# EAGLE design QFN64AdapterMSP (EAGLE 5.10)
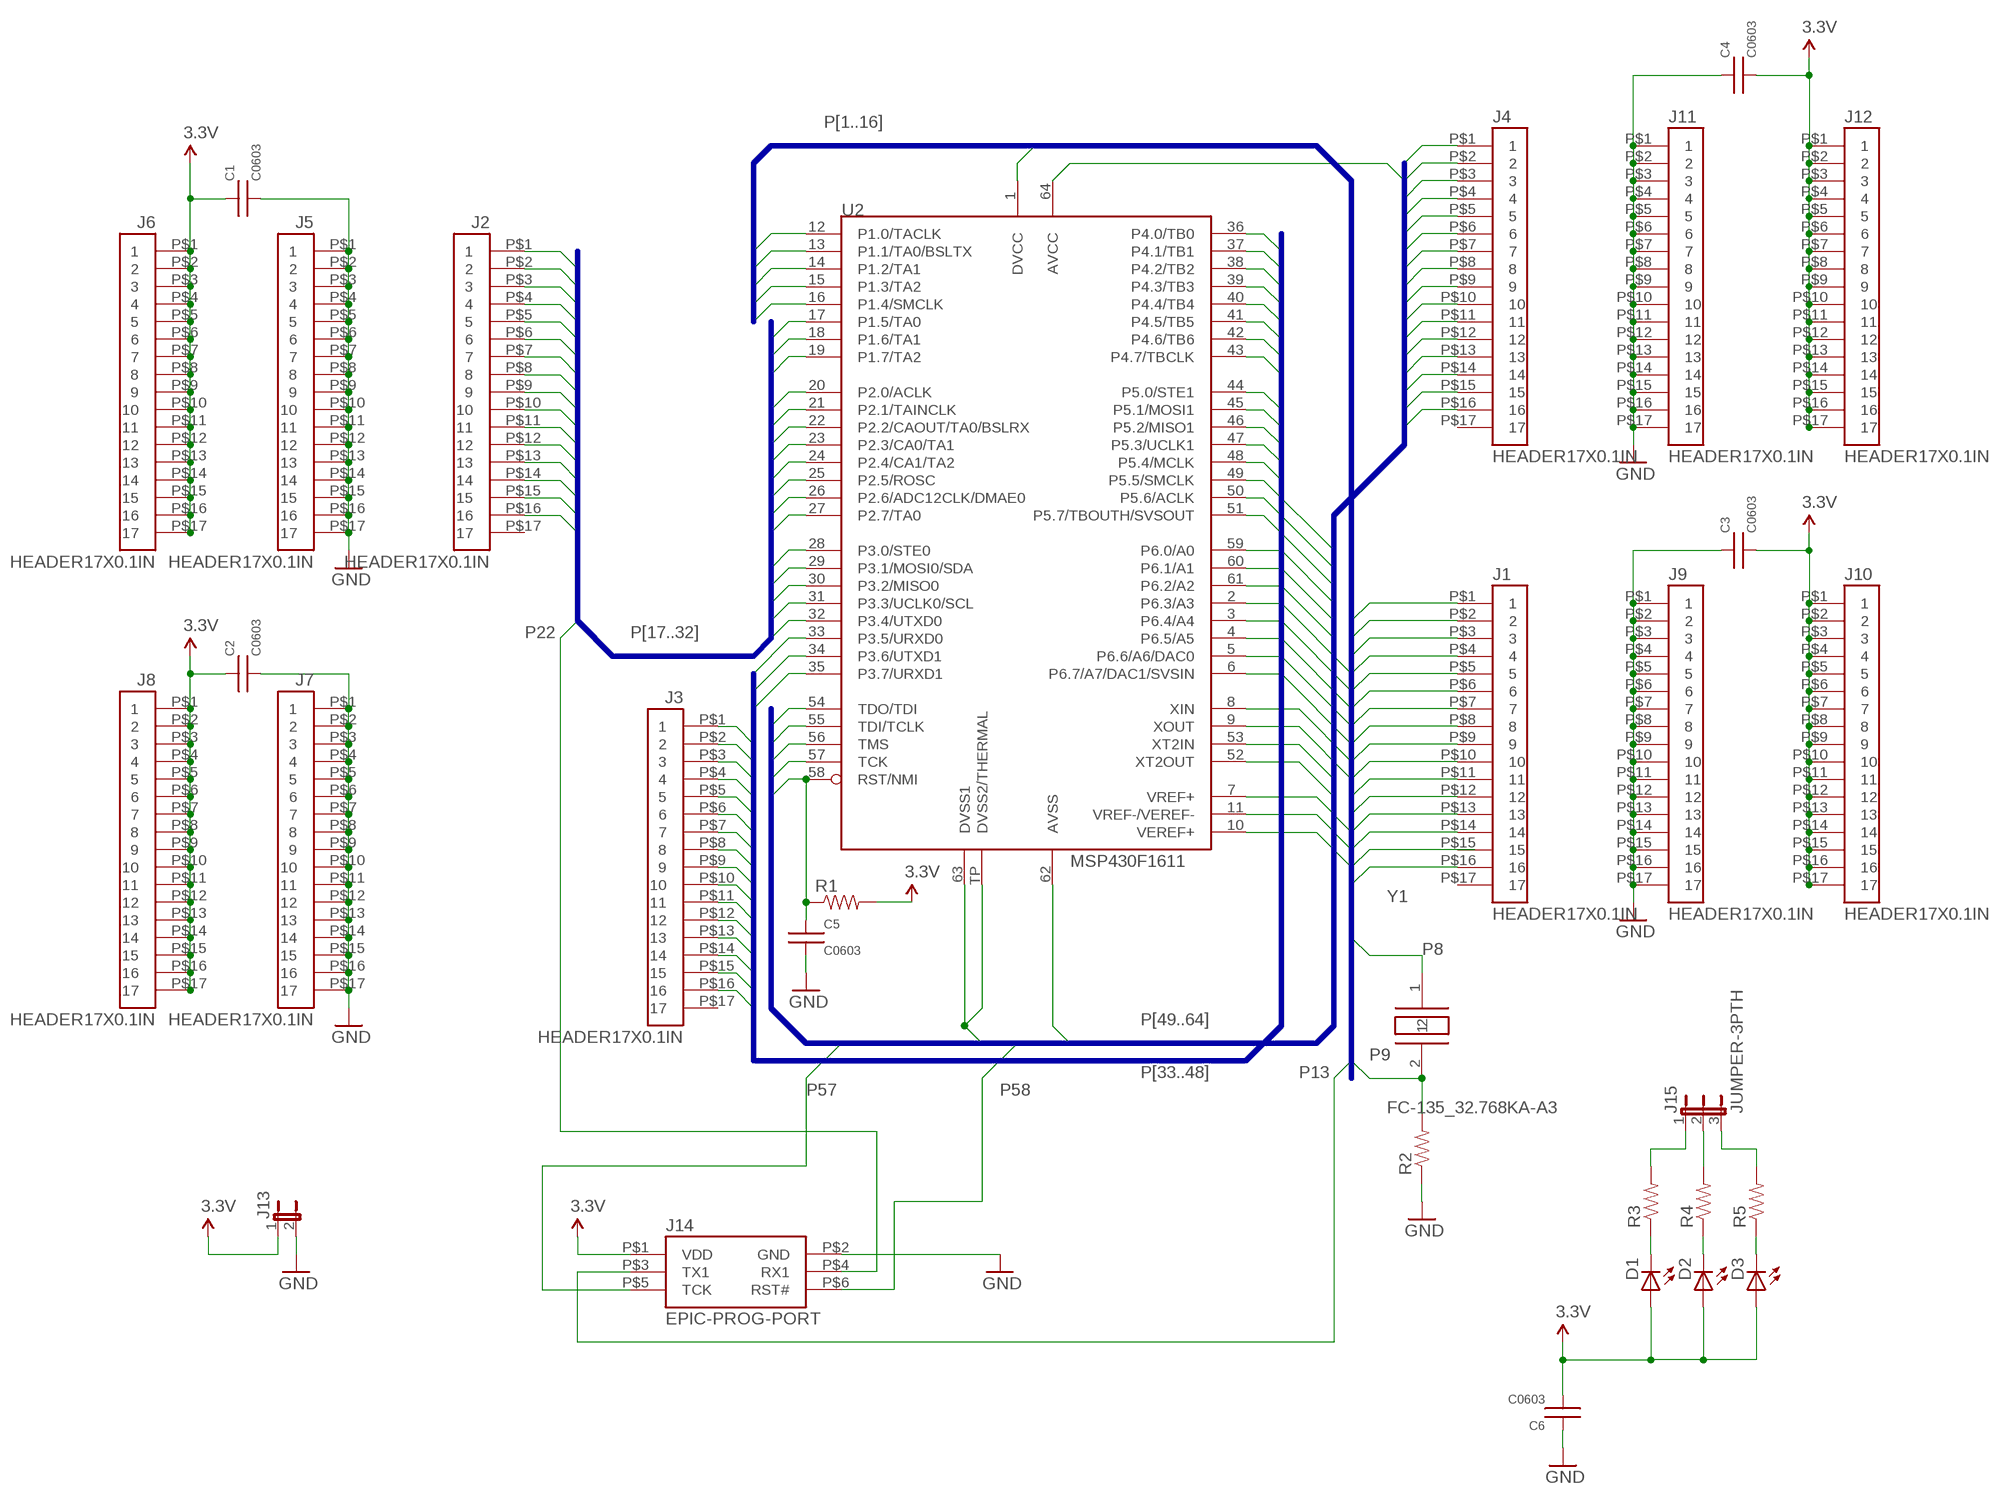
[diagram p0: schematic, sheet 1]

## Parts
C1  C0603  [C0603]
C2  C0603  [C0603]
C3  C0603  [C0603]
C4  C0603  [C0603]
C5  C0603  [C0603]
C6  C0603  [C0603]
D1  LED0603  [LED-0603]
D2  LED0603  [LED-0603]
D3  LED0603  [LED-0603]
J1  HEADER17X0.1IN  [HEADER17X0.1IN]
J2  HEADER17X0.1IN  [HEADER17X0.1IN]
J3  HEADER17X0.1IN  [HEADER17X0.1IN]
J4  HEADER17X0.1IN  [HEADER17X0.1IN]
J5  HEADER17X0.1IN  [HEADER17X0.1IN]
J6  HEADER17X0.1IN  [HEADER17X0.1IN]
J7  HEADER17X0.1IN  [HEADER17X0.1IN]
J8  HEADER17X0.1IN  [HEADER17X0.1IN]
J9  HEADER17X0.1IN  [HEADER17X0.1IN]
J10  HEADER17X0.1IN  [HEADER17X0.1IN]
J11  HEADER17X0.1IN  [HEADER17X0.1IN]
J12  HEADER17X0.1IN  [HEADER17X0.1IN]
J13  JUMPER-2PTH  [1X02]
J14  EPIC-PROG-PORT  [HEADER2X3X2MM]
J15  JUMPER-3PTH  [1X03]
R1  RESISTOR0603-RES  [0603-RES]
R2  RESISTOR0603-RES  [0603-RES]
R3  RESISTOR0603-RES  [0603-RES]
R4  RESISTOR0603-RES  [0603-RES]
R5  RESISTOR0603-RES  [0603-RES]
U2  MSP430F1611  [RTD(S-PQFP-N64)[VQFN64]]
Y1  FC-135_32.768KA-A3  [FC-135]

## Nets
3.3V: C1.1 C2.1 C3.2 C4.2 C6.2 D1.A D2.A D3.A J6.P$1 J6.P$2 J6.P$3 J6.P$4 J6.P$5 J6.P$6 J6.P$7 J6.P$8 J6.P$9 J6.P$10 J6.P$11 J6.P$12 J6.P$13 J6.P$14 J6.P$15 J6.P$16 J6.P$17 J8.P$1 J8.P$2 J8.P$3 J8.P$4 J8.P$5 J8.P$6 J8.P$7 J8.P$8 J8.P$9 J8.P$10 J8.P$11 J8.P$12 J8.P$13 J8.P$14 J8.P$15 J8.P$16 J8.P$17 J10.P$1 J10.P$2 J10.P$3 J10.P$4 J10.P$5 J10.P$6 J10.P$7 J10.P$8 J10.P$9 J10.P$10 J10.P$11 J10.P$12 J10.P$13 J10.P$14 J10.P$15 J10.P$16 J10.P$17 J12.P$1 J12.P$2 J12.P$3 J12.P$4 J12.P$5 J12.P$6 J12.P$7 J12.P$8 J12.P$9 J12.P$10 J12.P$11 J12.P$12 J12.P$13 J12.P$14 J12.P$15 J12.P$16 J12.P$17 J13.1 J14.P$1(VDD) R1.2
GND: C1.2 C2.2 C3.1 C4.1 C5.2 C6.1 J5.P$1 J5.P$2 J5.P$3 J5.P$4 J5.P$5 J5.P$6 J5.P$7 J5.P$8 J5.P$9 J5.P$10 J5.P$11 J5.P$12 J5.P$13 J5.P$14 J5.P$15 J5.P$16 J5.P$17 J7.P$1 J7.P$2 J7.P$3 J7.P$4 J7.P$5 J7.P$6 J7.P$7 J7.P$8 J7.P$9 J7.P$10 J7.P$11 J7.P$12 J7.P$13 J7.P$14 J7.P$15 J7.P$16 J7.P$17 J9.P$1 J9.P$2 J9.P$3 J9.P$4 J9.P$5 J9.P$6 J9.P$7 J9.P$8 J9.P$9 J9.P$10 J9.P$11 J9.P$12 J9.P$13 J9.P$14 J9.P$15 J9.P$16 J9.P$17 J11.P$1 J11.P$2 J11.P$3 J11.P$4 J11.P$5 J11.P$6 J11.P$7 J11.P$8 J11.P$9 J11.P$10 J11.P$11 J11.P$12 J11.P$13 J11.P$14 J11.P$15 J11.P$16 J11.P$17 J13.2 J14.P$2(GND) R2.1
N$1: D1.C R3.1
N$2: D2.C R4.1
N$3: D3.C R5.1
N$4: J15.1 R3.2
N$5: J15.2 R4.2
N$6: J15.3 R5.2
P1: J1.P$1 U2.1(DVCC)
P2: J1.P$2 U2.2(P6.3/A3)
P3: J1.P$3 U2.3(P6.4/A4)
P4: J1.P$4 U2.4(P6.5/A5)
P5: J1.P$5 U2.5(P6.6/A6/DAC0)
P6: J1.P$6 U2.6(P6.7/A7/DAC1/SVSIN)
P7: J1.P$7 U2.7(VREF+)
P8: J1.P$8 U2.8(XIN) Y1.1
P9: J1.P$9 R2.2 U2.9(XOUT) Y1.2
P10: J1.P$10 U2.10(VEREF+)
P11: J1.P$11 U2.11(VREF-/VEREF-)
P12: J1.P$12 U2.12(P1.0/TACLK)
P13: J1.P$13 J14.P$3(TX1) U2.13(P1.1/TA0/BSLTX)
P14: J1.P$14 U2.14(P1.2/TA1)
P15: J1.P$15 U2.15(P1.3/TA2)
P16: J1.P$16 U2.16(P1.4/SMCLK)
P17: J2.P$1 U2.17(P1.5/TA0)
P18: J2.P$2 U2.18(P1.6/TA1)
P19: J2.P$3 U2.19(P1.7/TA2)
P20: J2.P$4 U2.20(P2.0/ACLK)
P21: J2.P$5 U2.21(P2.1/TAINCLK)
P22: J2.P$6 J14.P$4(RX1) U2.22(P2.2/CAOUT/TA0/BSLRX)
P23: J2.P$7 U2.23(P2.3/CA0/TA1)
P24: J2.P$8 U2.24(P2.4/CA1/TA2)
P25: J2.P$9 U2.25(P2.5/ROSC)
P26: J2.P$10 U2.26(P2.6/ADC12CLK/DMAE0)
P27: J2.P$11 U2.27(P2.7/TA0)
P28: J2.P$12 U2.28(P3.0/STE0)
P29: J2.P$13 U2.29(P3.1/MOSI0/SDA)
P30: J2.P$14 U2.30(P3.2/MISO0)
P31: J2.P$15 U2.31(P3.3/UCLK0/SCL)
P32: J2.P$16 U2.32(P3.4/UTXD0)
P33: J3.P$1 U2.33(P3.5/URXD0)
P34: J3.P$2 U2.34(P3.6/UTXD1)
P35: J3.P$3 U2.35(P3.7/URXD1)
P36: J3.P$4 U2.36(P4.0/TB0)
P37: J3.P$5 U2.37(P4.1/TB1)
P38: J3.P$6 U2.38(P4.2/TB2)
P39: J3.P$7 U2.39(P4.3/TB3)
P40: J3.P$8 U2.40(P4.4/TB4)
P41: J3.P$9 U2.41(P4.5/TB5)
P42: J3.P$10 U2.42(P4.6/TB6)
P43: J3.P$11 U2.43(P4.7/TBCLK)
P44: J3.P$12 U2.44(P5.0/STE1)
P45: J3.P$13 U2.45(P5.1/MOSI1)
P46: J3.P$14 U2.46(P5.2/MISO1)
P47: J3.P$15 U2.47(P5.3/UCLK1)
P48: J3.P$16 U2.48(P5.4/MCLK)
P49: J4.P$1 U2.49(P5.5/SMCLK)
P50: J4.P$2 U2.50(P5.6/ACLK)
P51: J4.P$3 U2.51(P5.7/TBOUTH/SVSOUT)
P52: J4.P$4 U2.52(XT2OUT)
P53: J4.P$5 U2.53(XT2IN)
P54: J4.P$6 U2.54(TDO/TDI)
P55: J4.P$7 U2.55(TDI/TCLK)
P56: J4.P$8 U2.56(TMS)
P57: J4.P$9 J14.P$5(TCK) U2.57(TCK)
P58: C5.1 J4.P$10 J14.P$6(RST#) R1.1 U2.58(RST/NMI)
P59: J4.P$11 U2.59(P6.0/A0)
P60: J4.P$12 U2.60(P6.1/A1)
P61: J4.P$13 U2.61(P6.2/A2)
P62: J4.P$14 U2.62(AVSS)
P63: J4.P$15 U2.63(DVSS1) U2.TP(DVSS2/THERMAL)
P64: J4.P$16 U2.64(AVCC)
Unconnected: J1.P$17 J2.P$17 J3.P$17 J4.P$17

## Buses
P[17..32]
P[33..48]
P[49..64]
P[1..16]

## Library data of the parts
C1-C6 = umich:C
D1-D3 = umich:LED: LEDs
J1-J12 = berkeley-epic:HEADER17X0.1IN
J13 = umich:JUMPER-2: Jumper
J14 = berkeley-epic:EPIC-PROG-PORT
J15 = umich:JUMPER-3
R1-R5 = SparkFun:RESISTOR: Resistor
U2 = Thomas:MSP430F1611
Y1 = berkeley-epic:FC-135_32.768KA-A3

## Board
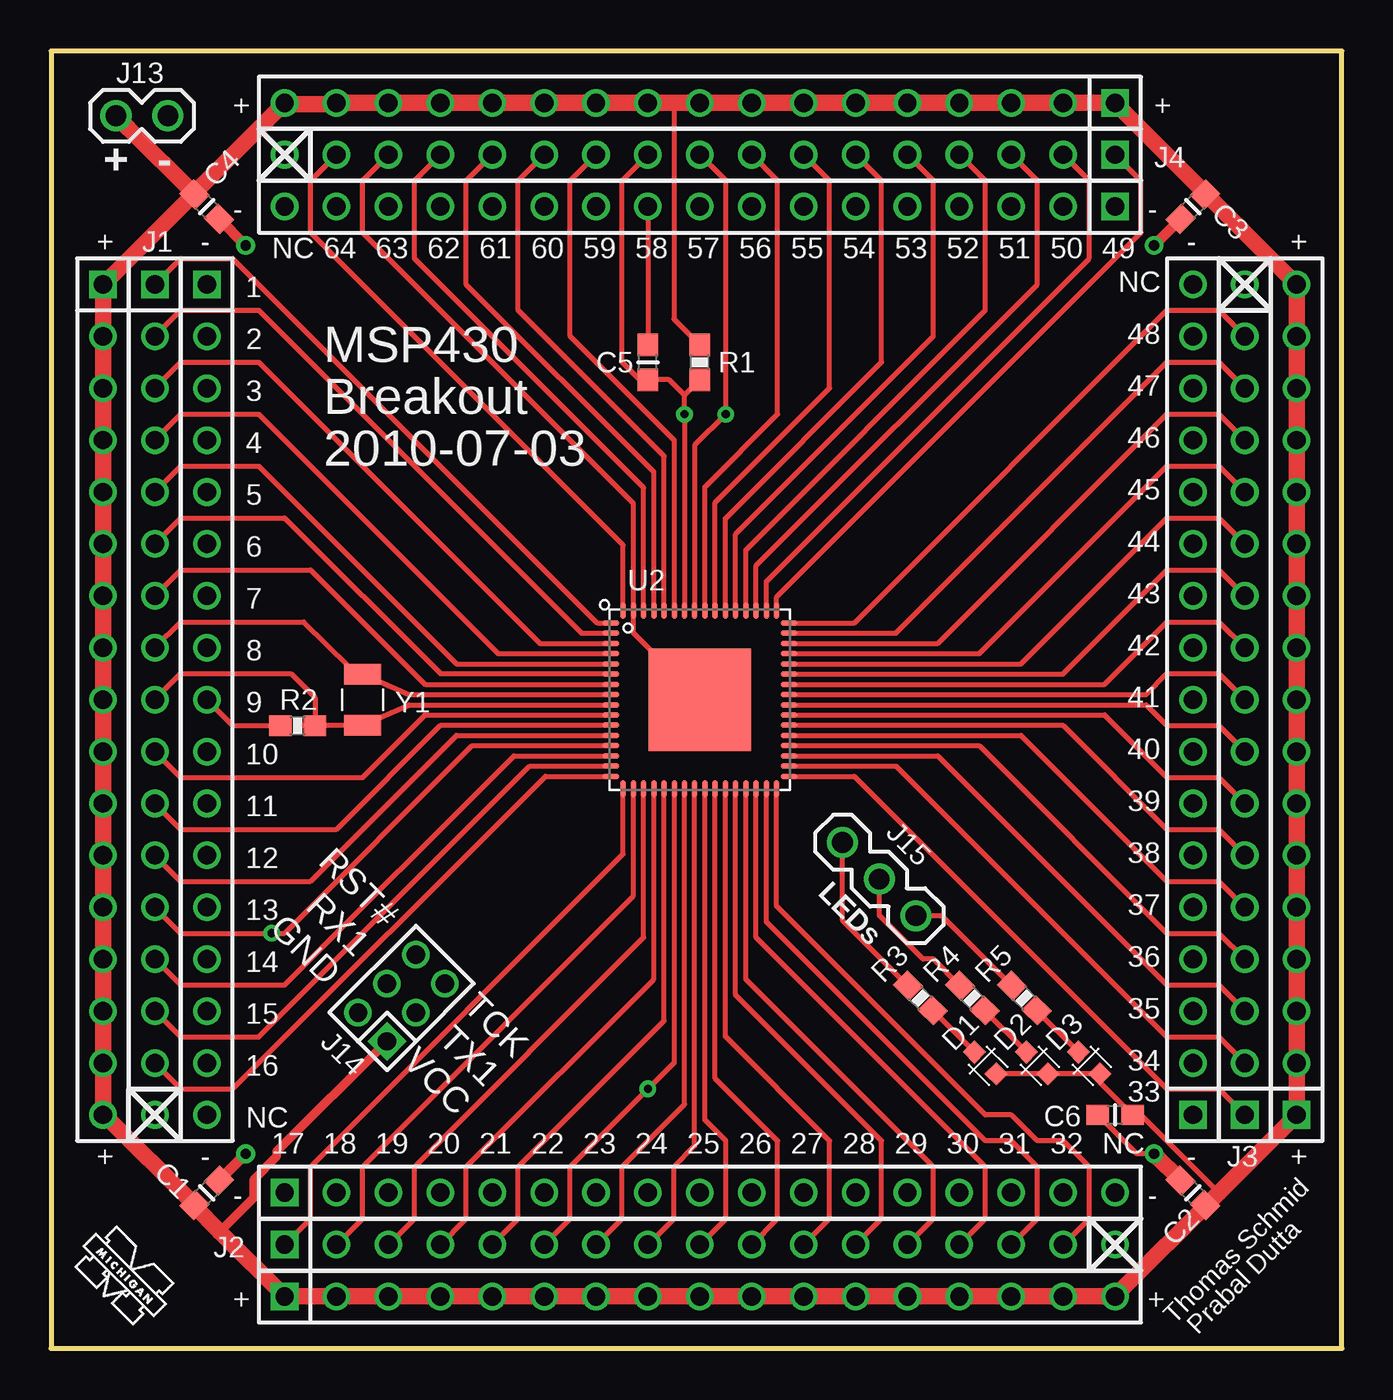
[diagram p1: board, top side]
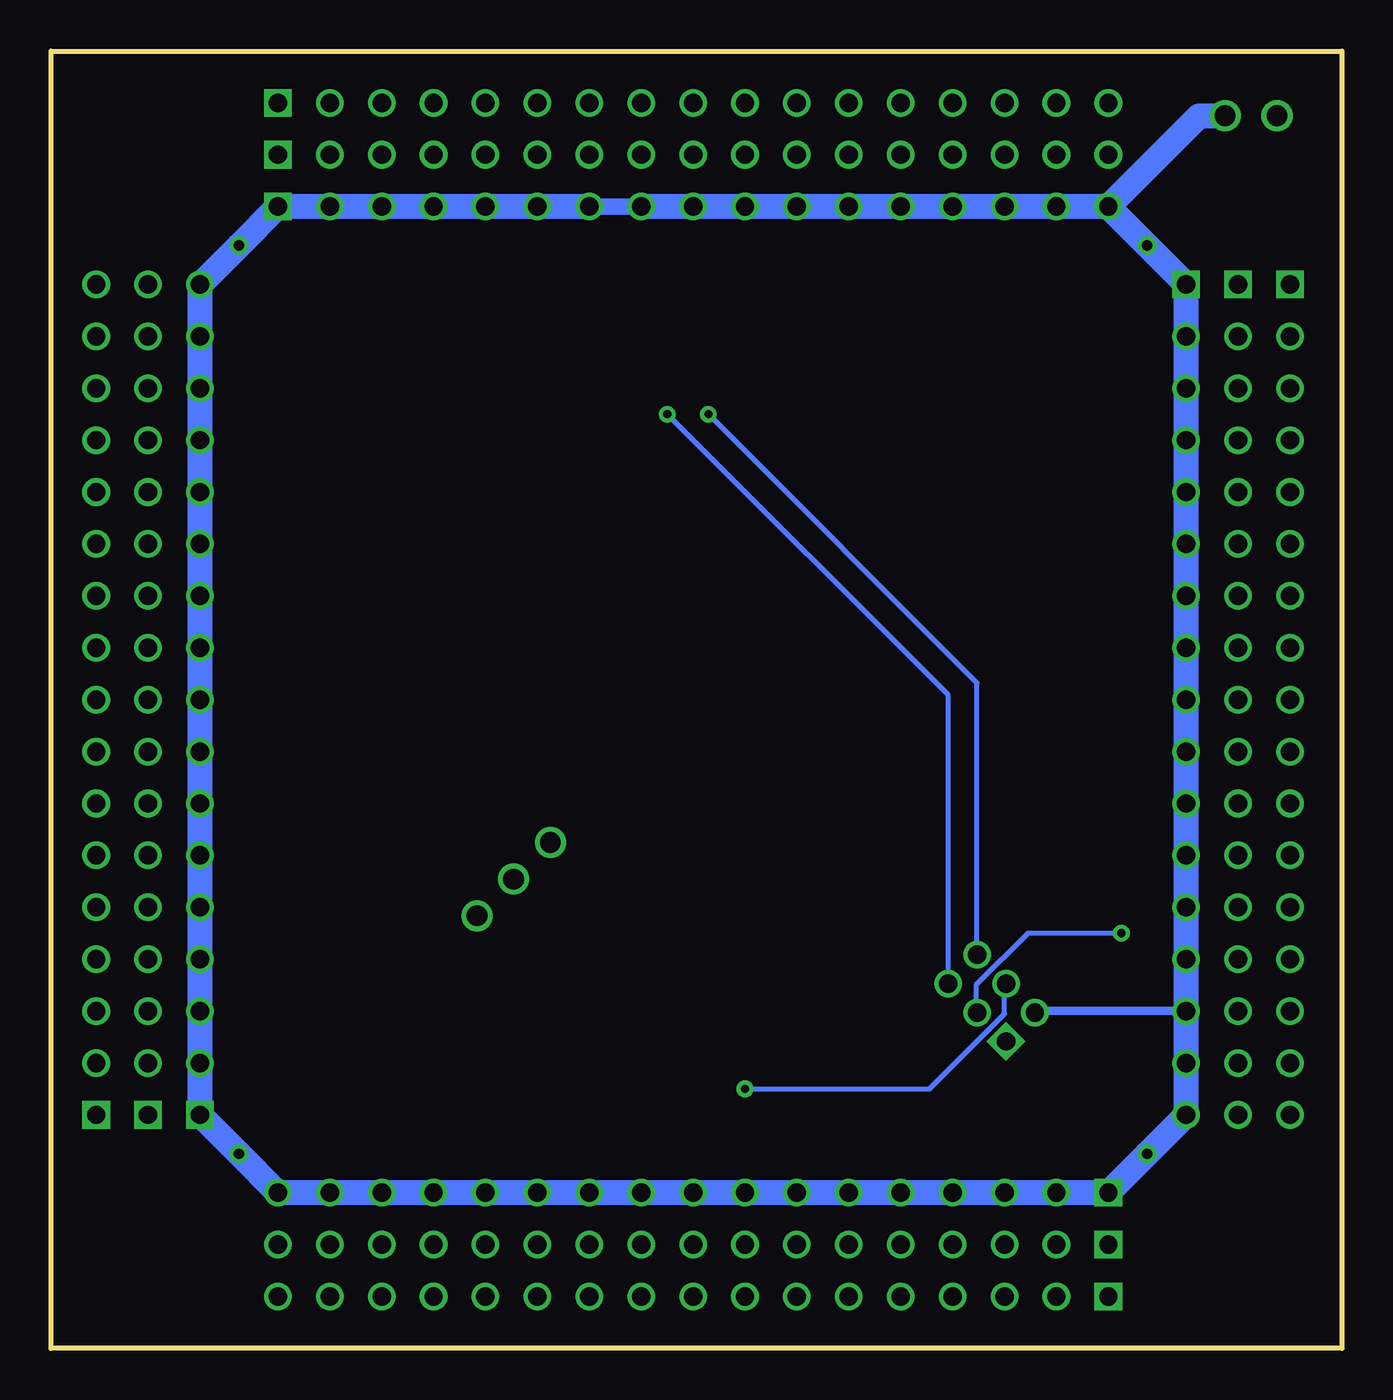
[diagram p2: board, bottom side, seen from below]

Size 63.17 x 63.49 mm. Coordinates in mm from the lower left corner, seen from the top.
Outline: 0,0 63.17,0 63.17,63.49 0,63.49 0,0
Copper layers (1*16): Top 0.0178mm / dielectric 1.4986mm / Bottom 0.0178mm
Design rules "SSC-EAGLE-2Lyr_v1.0.0.3": minimum track width 6mil, minimum drill 14mil, track to track 6mil, track to pad 6mil, pad to pad 6mil, via to via 6mil, smd to smd 6mil, copper to edge 20mil, drill to drill 16mil, minimum pad ring 8mil, minimum via ring 8mil, stop-mask expansion 3mil, vias tented up to drill 0mil, thermal gap 10mil

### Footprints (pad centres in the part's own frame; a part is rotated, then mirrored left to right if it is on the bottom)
C0603 = smd 1.1 x 1: 1 -0.85,0; 2 0.85,0
LED-0603 = smd 0.8 x 0.8: A 0,-0.75; C 0,0.75
HEADER17X0.1IN = drill 0.9 square: P$1 -20.32,0 | drill 0.9 round: P$2 -17.78,0; P$3 -15.24,0; P$4 -12.7,0; P$5 -10.16,0; P$6 -7.62,0; P$7 -5.08,0; P$8 -2.54,0; P$9 0,0; P$10 2.54,0; P$11 5.08,0; P$12 7.62,0; P$13 10.16,0; P$14 12.7,0; P$15 15.24,0; P$16 17.78,0; P$17 20.32,0
1X02 = drill 1.016 round: 1 0,0; 2 2.54,0
HEADER2X3X2MM = drill 0.9 square: P$1 -1,2 | drill 0.9 round: P$2 1,2; P$3 -1,0; P$4 1,0; P$5 -1,-2; P$6 1,-2
1X03 = drill 1.016 round: 1 0,0; 2 2.54,0; 3 5.08,0
0603-RES = smd 1.1 x 1: 1 -0.85,0; 2 0.85,0
RTD(S-PQFP-N64)[VQFN64] = smd 0.825 x 0.28: 1 -4.36,3.75; 2 -4.36,3.25; 3 -4.36,2.75; 4 -4.36,2.25; 5 -4.36,1.75; 6 -4.36,1.25; 7 -4.36,0.75; 8 -4.36,0.25; 9 -4.36,-0.25; 10 -4.36,-0.75; 11 -4.36,-1.25; 12 -4.36,-1.75; 13 -4.36,-2.25; 14 -4.36,-2.75; 15 -4.36,-3.25; 16 -4.36,-3.75; 33 4.36,-3.75; 34 4.36,-3.25; 35 4.36,-2.75; 36 4.36,-2.25; 37 4.36,-1.75; 38 4.36,-1.25; 39 4.36,-0.75; 40 4.36,-0.25; 41 4.36,0.25; 42 4.36,0.75; 43 4.36,1.25; 44 4.36,1.75; 45 4.36,2.25; 46 4.36,2.75; 47 4.36,3.25; 48 4.36,3.75 | smd 0.28 x 0.825: 17 -3.75,-4.36; 18 -3.25,-4.36; 19 -2.75,-4.36; 20 -2.25,-4.36; 21 -1.75,-4.36; 22 -1.25,-4.36; 23 -0.75,-4.36; 24 -0.25,-4.36; 25 0.25,-4.36; 26 0.75,-4.36; 27 1.25,-4.36; 28 1.75,-4.36; 29 2.25,-4.36; 30 2.75,-4.36; 31 3.25,-4.36; 32 3.75,-4.36; 49 3.75,4.36; 50 3.25,4.36; 51 2.75,4.36; 52 2.25,4.36; 53 1.75,4.36; 54 1.25,4.36; 55 0.75,4.36; 56 0.25,4.36; 57 -0.25,4.36; 58 -0.75,4.36; 59 -1.25,4.36; 60 -1.75,4.36; 61 -2.25,4.36; 62 -2.75,4.36; 63 -3.25,4.36; 64 -3.75,4.36 | smd 5 x 5: TP 0,0
FC-135 = smd 1 x 1.8: 1 -1.25,0; 2 1.25,0

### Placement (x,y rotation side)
C1  7.62,7.62 45 top
C2  55.88,7.62 135 top
C3  55.88,55.88 45 top
C4  7.62,55.88 135 top
C5  29.21,48.26 90 top
C6  52.07,11.43 0 top
D1  45.72,13.97 45 top
D2  48.26,13.97 45 top
D3  50.8,13.97 45 top
J1  5.08,31.75 270 top
J2  31.75,5.08 0 top
J3  58.42,31.75 90 top
J4  31.75,58.42 180 top
J5  31.75,7.62 0 top
J6  31.75,2.54 0 top
J7  55.88,31.75 90 top
J8  60.96,31.75 90 top
J9  7.62,31.75 270 top
J10  2.54,31.75 270 top
J11  31.75,55.88 180 top
J12  31.75,60.96 180 top
J13  3.17,60.33 0 top
J14  17.14,17.14 135 top
J15  38.73,24.77 315 top
R1  31.75,48.26 90 top
R2  12.06,30.48 0 top
R3  42.55,17.14 135 top
R4  45.09,17.14 135 top
R5  47.62,17.14 135 top
U2  31.75,31.75 0 top
U$2  [UMICH]  0.64,4.19 315 top
Y1  15.24,31.75 270 top

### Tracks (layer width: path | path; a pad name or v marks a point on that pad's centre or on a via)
3.3V
  Top 0.254: R1.2 30.48,50.38 30.48,60.96 | C2.1 57.08,7.62 57.15,7.62 53.34,11.43 C6.2 51.33,13.02 D3.A D2.A D1.A | J8.P$17 60.89,52.07 C3.2 | J12.P$16 13.9,60.89 | J12.P$10 J12.P$9
  Top 0.406: 8.26,5.71 9.91,7.37 9.91,8.26 11.05,9.4 11.05,9.63 J14.P$1
  Top 0.508: 2.61,11.43 J10.P$17 | C1.1 7.02,6.95 | J10.P$13 J10.P$12 2.54,25.4 | C4.2 11.43,60.89 J12.P$17 J12.P$16 | J12.P$10 30.48,60.96 J12.P$9 J12.P$8 | J12.P$5 J12.P$4 J12.P$3
  Top 0.813: 7.02,6.95 8.26,5.71 J6.P$1 J6.P$2 J6.P$3 J6.P$4 J6.P$5 J6.P$6 J6.P$7 J6.P$8 J6.P$9 J6.P$10 J6.P$11 J6.P$12 J6.P$13 J6.P$14 J6.P$15 J6.P$16 J6.P$17 57.15,7.62 J8.P$1 J8.P$2 J8.P$3 J8.P$4 J8.P$5 J8.P$6 J8.P$7 J8.P$8 J8.P$9 J8.P$10 J8.P$11 J8.P$12 J8.P$13 J8.P$14 J8.P$15 J8.P$16 J8.P$17 J12.P$1 J12.P$2 J12.P$3 J12.P$5 J12.P$6 J12.P$7 J12.P$8 J12.P$10 J12.P$11 J12.P$12 J12.P$13 J12.P$14 J12.P$15 J12.P$16 | J10.P$17 J10.P$16 J10.P$15 J10.P$14 J10.P$13 2.54,25.4 J10.P$11 J10.P$10 J10.P$9 J10.P$8 J10.P$7 J10.P$6 J10.P$5 J10.P$4 J10.P$3 J10.P$2 J10.P$1 J12.P$17 | J13.1 3.81,59.69 C4.2 | C1.1 2.61,11.43 | 11.43,60.89 13.9,60.89
GND  (via drill 0.51)
  Top 0.254: R2.1 8.89,30.48 J9.P$9 | J11.P$10 C5.2 | v53.98,9.53 53.12,9.53 C6.1
  Top 0.508: C1.2 v9.53,9.53 | v9.53,53.98 C4.1 | v53.98,53.98 C3.1
  Top 0.813: v53.98,9.53 C2.2
  Bottom 0.406: J9.P$15 14.95,16.51 J14.P$2
  Bottom 0.508: J5.P$13 J5.P$14 J5.P$15
  Bottom 0.813: J11.P$8 J11.P$7
  Bottom 1.219: J11.P$17 J11.P$16 J11.P$15 J11.P$14 J11.P$13 J11.P$12 J11.P$11 J11.P$10 J11.P$9 J11.P$8 | J11.P$7 J11.P$6 J11.P$5 J11.P$4 J11.P$3 J11.P$2 J11.P$1 v53.98,53.98 J7.P$17 J7.P$16 J7.P$15 J7.P$14 J7.P$13 J7.P$12 J7.P$11 J7.P$10 J7.P$9 J7.P$8 J7.P$7 J7.P$6 J7.P$5 J7.P$4 J7.P$3 J7.P$2 J7.P$1 v53.98,9.53 J5.P$17 J5.P$16 J5.P$15 J5.P$13 J5.P$12 J5.P$11 J5.P$10 J5.P$9 J5.P$8 J5.P$7 J5.P$6 J5.P$5 J5.P$4 J5.P$3 J5.P$2 J5.P$1 v9.53,9.53 J9.P$17 J9.P$16 J9.P$15 J9.P$14 J9.P$13 J9.P$12 J9.P$11 J9.P$10 J9.P$9 J9.P$8 J9.P$7 J9.P$6 J9.P$5 J9.P$4 J9.P$3 J9.P$2 J9.P$1 v9.53,53.98 J11.P$17 | J11.P$17 6.99,60.33 J13.2
N$1
  Top 0.254: D1.C R3.1
N$2
  Top 0.254: D2.C R4.1
N$3
  Top 0.254: D3.C R5.1
N$4
  Top 0.254: J15.1 38.73,20.95 R3.2
N$5
  Top 0.254: J15.2 40.53,21.19 42.67,19.05 43.18,19.05 R4.2
N$6
  Top 0.254: J15.3 43.6,21.17 R5.2
P1
  Top 0.254: U2.1 26.73,35.5 8.89,53.34 6.35,53.34 J1.P$1
P2
  Top 0.254: U2.2 25.96,35 10.16,50.8 6.35,50.8 J1.P$2
P3
  Top 0.254: U2.3 23.92,34.5 10.16,48.26 6.35,48.26 J1.P$3
P4
  Top 0.254: U2.4 21.88,34 10.16,45.72 6.35,45.72 J1.P$4
P5
  Top 0.254: U2.5 19.84,33.5 10.16,43.18 6.35,43.18 J1.P$5
P6
  Top 0.254: J1.P$6 6.35,40.64 11.43,40.64 19.05,33.02 27.37,33.02 U2.6
P7
  Top 0.254: J1.P$7 6.35,38.1 12.7,38.1 18.3,32.5 U2.7
P8
  Top 0.254: U2.8 17.51,32 Y1.1 14.94,33 14.61,33.34 12.36,35.56 6.35,35.56 J1.P$8
P9
  Top 0.254: U2.9 17.51,31.5 Y1.2 12.3,30.5 R2.2 12.91,31.85 11.75,33.02 6.35,33.02 J1.P$9
P10
  Top 0.254: U2.10 18.3,31 15.24,27.94 6.35,27.94 J1.P$10
P11
  Top 0.254: U2.11 19.07,30.5 13.97,25.4 6.35,25.4 J1.P$11
P12
  Top 0.254: U2.12 19.84,30 12.7,22.86 6.35,22.86 J1.P$12
P13  (via drill 0.41)
  Top 0.254: U2.13 20.61,29.5 11.43,20.32 v10.79,20.32 6.35,20.32 J1.P$13
  Bottom 0.254: J14.P$3 17.85,16.45 17.91,16.51 17.91,17.78 15.37,20.32 v10.79,20.32
P14
  Top 0.254: U2.14 22.65,29 11.43,17.78 6.35,17.78 J1.P$14
P15
  Top 0.254: U2.15 23.42,28.5 10.16,15.24 6.35,15.24 J1.P$15
P16
  Top 0.254: U2.16 24.19,28 8.89,12.7 6.35,12.7 J1.P$16
P17
  Top 0.254: U2.17 28,24.19 12.7,8.89 12.7,6.35 J2.P$1
P18
  Top 0.254: U2.18 28.5,22.15 15.24,8.89 15.24,6.35 J2.P$2
P19
  Top 0.254: U2.19 29,20.11 17.78,8.89 17.78,6.35 J2.P$3
P20
  Top 0.254: U2.20 29.5,18.07 20.32,8.89 20.32,6.35 J2.P$4
P21
  Top 0.254: U2.21 30,16.03 22.86,8.89 22.86,6.35 J2.P$5
P22  (via drill 0.41)
  Top 0.254: U2.22 30.5,13.99 v29.21,12.7 25.4,8.89 25.4,6.35 J2.P$6
  Bottom 0.254: J14.P$4 16.51,17.78 16.51,16.38 20.19,12.7 v29.21,12.7 | J14.P$4
P23
  Top 0.254: U2.23 31,11.95 27.94,8.89 27.94,6.35 J2.P$7
P24
  Top 0.254: U2.24 31.5,9.91 30.48,8.89 30.48,6.35 J2.P$8
P25
  Top 0.254: U2.25 32,11.18 33.02,10.16 33.02,6.35 J2.P$9
P26
  Top 0.254: U2.26 32.5,13.22 35.56,10.16 35.56,6.35 J2.P$10
P27
  Top 0.254: U2.27 33,15.26 38.1,10.16 38.1,6.35 J2.P$11
P28
  Top 0.254: U2.28 33.5,17.3 40.64,10.16 40.64,6.35 J2.P$12
P29
  Top 0.254: U2.29 34,18.07 43.18,8.89 43.18,6.35 J2.P$13
P30
  Top 0.254: J2.P$14 45.72,6.35 45.72,8.89 34.5,20.11 U2.30
P31
  Top 0.254: J2.P$15 48.26,6.35 48.26,8.89 46.99,10.16 45.72,10.16 35,20.88 U2.31
P32
  Top 0.254: J2.P$16 50.8,6.35 50.8,8.89 49.53,10.16 48.26,10.16 46.99,11.43 45.72,11.43 35.5,21.65 U2.32
P33
  Top 0.254: J3.P$1 57.15,12.7 54.61,12.7 39.31,28 U2.33
P34
  Top 0.254: U2.34 41.35,28.5 54.61,15.24 57.15,15.24 J3.P$2
P35
  Top 0.254: U2.35 43.39,29 54.61,17.78 57.15,17.78 J3.P$3
P36
  Top 0.254: U2.36 45.43,29.5 54.61,20.32 57.15,20.32 J3.P$4
P37
  Top 0.254: U2.37 47.47,30 54.61,22.86 57.15,22.86 J3.P$5
P38
  Top 0.254: U2.38 49.51,30.5 54.61,25.4 57.15,25.4 J3.P$6
P39
  Top 0.254: U2.39 51.55,31 54.61,27.94 57.15,27.94 J3.P$7
P40
  Top 0.254: U2.40 53.59,31.5 54.61,30.48 57.15,30.48 J3.P$8
P41
  Top 0.254: U2.41 53.59,32 54.61,33.02 57.15,33.02 J3.P$9
P42
  Top 0.254: U2.42 51.55,32.5 54.61,35.56 57.15,35.56 J3.P$10
P43
  Top 0.254: U2.43 49.51,33 54.61,38.1 57.15,38.1 J3.P$11
P44
  Top 0.254: U2.44 47.47,33.5 54.61,40.64 57.15,40.64 J3.P$12
P45
  Top 0.254: U2.45 45.43,34 54.61,43.18 57.15,43.18 J3.P$13
P46
  Top 0.254: U2.46 43.39,34.5 54.61,45.72 57.15,45.72 J3.P$14
P47
  Top 0.254: U2.47 41.35,35 54.61,48.26 57.15,48.26 J3.P$15
P48
  Top 0.254: U2.48 39.31,35.5 54.61,50.8 57.15,50.8 J3.P$16
P49
  Top 0.254: U2.49 35.5,36.77 53.34,54.61 53.34,57.15 J4.P$1
P50
  Top 0.254: U2.50 35,37.54 50.8,53.34 50.8,57.15 J4.P$2
P51
  Top 0.254: U2.51 34.5,38.31 48.26,52.07 48.26,57.15 J4.P$3
P52
  Top 0.254: U2.52 34,39.08 45.72,50.8 45.72,57.15 J4.P$4
P53
  Top 0.254: U2.53 33.5,39.85 43.18,49.53 43.18,57.15 J4.P$5
P54
  Top 0.254: U2.54 33,40.62 40.64,48.26 40.64,57.15 J4.P$6
P55
  Top 0.254: U2.55 32.5,41.39 38.1,46.99 38.1,57.15 J4.P$7
P56
  Top 0.254: J4.P$8 35.56,57.15 35.56,45.72 32,42.16 U2.56
P57  (via drill 0.41)
  Top 0.254: U2.57 31.5,44.2 v33.02,45.72 33.02,57.15 J4.P$9
  Bottom 0.254: J14.P$5 19.27,31.97 v33.02,45.72
P58  (via drill 0.41)
  Top 0.254: U2.58 v31,45.72 31,46.66 | 31,46.66 30.25,47.41 C5.1 28.79,47.41 27.94,48.26 27.94,57.15 J4.P$10 | 31,46.66 R1.1
  Bottom 0.254: J14.P$6 17.85,32.57 v31,45.72
P59
  Top 0.254: U2.59 30.5,44.43 25.4,49.53 25.4,57.15 J4.P$11
P60
  Top 0.254: U2.60 30,43.66 22.86,50.8 22.86,57.15 J4.P$12
P61
  Top 0.254: U2.61 29.5,42.89 20.32,52.07 20.32,57.15 J4.P$13
P62
  Top 0.254: U2.62 29,42.12 17.78,53.34 17.78,57.15 J4.P$14
P63
  Top 0.254: U2.TP 28.5,35 U2.63 28.5,41.35 15.24,54.61 15.24,57.15 J4.P$15
P64
  Top 0.254: U2.64 28,39.31 12.7,54.61 12.7,57.15 J4.P$16

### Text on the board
tPlace: + | + | + | - | - | - | + | - | - | + | NC | 64 | 63 | 62 | 61 | 60 | 59 | 58 | 57 | 56 | 55 | 54 | 53 | 52 | 51 | 50 | 49 | NC | 1 | 48 | 2 | MSP430 | 47 | 3 | Breakout | 46 | 4 | 2010-07-03 | 45 | 5 | 44 | 6 | 43 | 7 | 42 | 8 | 41 | 9 | 40 | 10 | 39 | 11 | 38 | 12 | LEDs | 37 | 13 | 36 | 14 | 35 | 15 | 34 | 16 | 33 | NC | 17 | 18 | 19 | 20 | 21 | 22 | 23 | 24 | 25 | 26 | 27 | 28 | 29 | 30 | 31 | 32 | NC | + | - | - | + | - | - | + | + | Thomas Schmid | Prabal Dutta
